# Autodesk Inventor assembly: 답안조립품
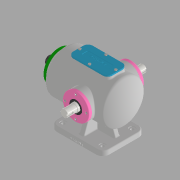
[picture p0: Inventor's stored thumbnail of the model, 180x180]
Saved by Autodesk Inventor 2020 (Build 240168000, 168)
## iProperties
Created: 2021-11
Part Number: 답안조립품
Document SubType Name: Assembly
Designer: Administrator
Author: Administrator
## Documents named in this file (14)
- C:\Users\Administrator\Desktop\711106v1027\답안조립품.iam
- C:\Users\Administrator\Desktop\711106v1027\본체.ipt
- C:\Users\Administrator\Desktop\711106v1027\베어링 6205.ipt
- 베어링 6205.ipt
- C:\Users\Administrator\Desktop\711106v1027\볼트 M4x0.7.ipt
- C:\Users\Administrator\Desktop\711106v1027\부시.ipt
- C:\Users\Administrator\Desktop\711106v1027\상부커버.ipt
- C:\Users\Administrator\Desktop\711106v1027\슬라이드 커버.ipt
- C:\Users\Administrator\Desktop\711106v1027\슬라이드.ipt
- C:\Users\Administrator\Desktop\711106v1027\오일실.ipt
- 오일실.ipt
- C:\Users\Administrator\Desktop\711106v1027\육각머리볼트 M4.ipt
- C:\Users\Administrator\Desktop\711106v1027\축 커버.ipt
- C:\Users\Administrator\Desktop\711106v1027\편심축.ipt
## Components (12 placed, 1 different names)
1. M4x0.7:1 — 각도:5
2. M4x0.7:4
3. M4x0.7:5
4. M4x0.7:6
5. M4x0.7:2 — 각도:6
6. M4x0.7:7
7. M4x0.7:8
8. M4x0.7:9
9. M4x0.7:3 — 각도:7
10. M4x0.7:10
11. M4x0.7:11
12. M4x0.7:12
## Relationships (3: Angle 3)
- 각도:5 [Angle]: M4x0.7:1
- 각도:6 [Angle]: M4x0.7:2
- 각도:7 [Angle]: M4x0.7:3
